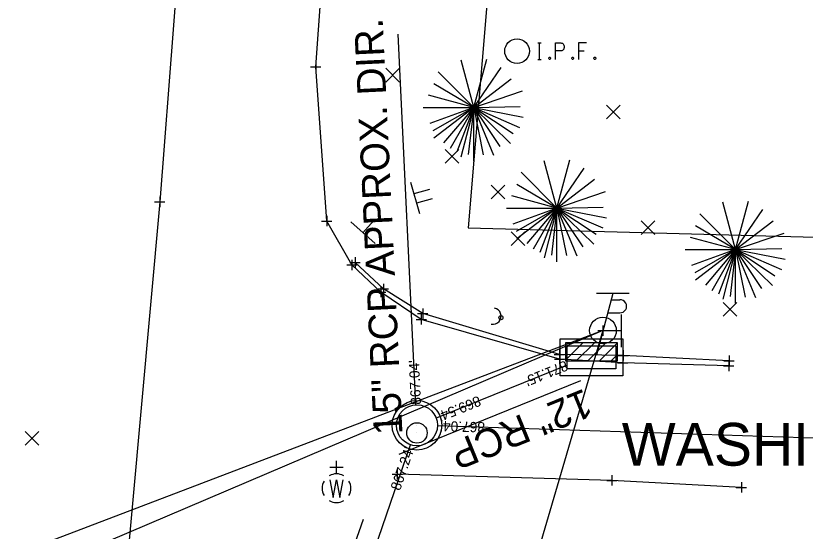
# Model space of a CAD drawing. Extents: x 1380550 to 1381945, y 468927 to 470496.
# Drawn here: x 1381608.3 to 1381685.3, y 470227.8 to 470278.1 of the extents above; entities that cross this region are included whole.
import ezdxf

# ---------------------------------------------------------------- set-up
doc = ezdxf.new("R2010")
doc.units = 0
for name, color, linetype in [('DR_X_Cells', 7, 'Continuous'), ('DR_X_Storm_Sewer', 7, 'Continuous'), ('DR_X_Text', 7, 'Continuous'), ('GK_Drainage_Nodes', 7, 'Continuous'), ('PV_X_COP', 7, 'Continuous'), ('PV_X_Curb', 7, 'Continuous'), ('PV_X_EOP', 7, 'Continuous'), ('RC_X_Text', 7, 'Continuous'), ('RW_X_Esmt_General', 7, 'Continuous'), ('SC_Scratch1', 7, 'Continuous'), ('SN_X_Public', 7, 'Continuous'), ('SV_X_Mon_Cells_Found', 7, 'Continuous'), ('SV_X_Random_Point', 7, 'Continuous'), ('SV_X_Shot_Marker', 7, 'Continuous'), ('UT_X_Electric', 7, 'Continuous'), ('UT_X_Misc_Cells', 7, 'Continuous'), ('UT_X_Telecom', 7, 'Continuous'), ('UT_X_Water_Cells', 7, 'Continuous'), ('VG_X_Cells', 7, 'Continuous')]:
    doc.layers.add(name, color=color, linetype=linetype)

msp = doc.modelspace()

# ---------------------------------------------------------------- linework, layer by layer
at = {"layer": 'DR_X_Cells'}
for p, q in [((1381662.499, 470246.25), (1381661.944, 470245.694)), ((1381663.629, 470246.25), (1381661.944, 470244.561)), ((1381664.759, 470246.25), (1381662.93, 470244.417)), ((1381665.888, 470246.25), (1381664.06, 470244.417)), ((1381666.944, 470246.176), (1381665.19, 470244.417)), ((1381666.944, 470245.043), (1381666.32, 470244.417))]:
    msp.add_line(p, q, dxfattribs=at)
for points in [[(1381667.486, 470242.999), (1381661.402, 470242.999), (1381661.402, 470246.583), (1381667.486, 470246.583)], [(1381666.944, 470244.417), (1381661.944, 470244.417), (1381661.944, 470246.25), (1381666.944, 470246.25)], [(1381666.819, 470243.667), (1381662.069, 470243.667), (1381662.069, 470245.917), (1381666.819, 470245.917)]]:
    msp.add_lwpolyline(points, close=True, dxfattribs=at)
for centre, radius in [((1381647.426, 470238.171), 2.417), ((1381647.426, 470238.171), 2), ((1381647.426, 470237.421), 1)]:
    msp.add_circle(centre, radius, dxfattribs=at)
at = {"layer": 'DR_X_Storm_Sewer'}
for p, q in [((1381647.33, 470240.169), (1381645.602, 470276.308)), ((1381662.069, 470244.042), (1381649.304, 470238.86)), ((1381940.268, 470228.716), (1381649.425, 470238.106)), ((1381633.903, 470198.558), (1381646.794, 470236.273))]:
    msp.add_line(p, q, dxfattribs=at)
at = {"layer": 'DR_X_Text'}
for p, q in [((1381645.705, 470235.349), (1381663.39, 470242.528)), ((1381642.166, 470228.993), (1381635.993, 470210.933))]:
    msp.add_line(p, q, dxfattribs=at)
at = {"layer": 'GK_Drainage_Nodes'}
for p, q in [((1381664.444, 470246.583), (1381664.444, 470246.583)), ((1381664.444, 470245.917), (1381664.444, 470245.917)), ((1381662.069, 470244.792), (1381662.069, 470244.792)), ((1381664.444, 470244.792), (1381664.444, 470244.792)), ((1381666.819, 470244.792), (1381666.819, 470244.792)), ((1381664.444, 470244.417), (1381664.444, 470244.417)), ((1381664.444, 470244.417), (1381664.444, 470244.417)), ((1381664.444, 470243.667), (1381664.444, 470243.667)), ((1381664.444, 470243), (1381664.444, 470243)), ((1381647.426, 470240.171), (1381647.426, 470240.171)), ((1381647.426, 470238.171), (1381647.426, 470238.171)), ((1381647.426, 470238.171), (1381647.426, 470238.171)), ((1381647.426, 470237.421), (1381647.426, 470237.421)), ((1381647.426, 470236.171), (1381647.426, 470236.171))]:
    msp.add_line(p, q, dxfattribs=at)
msp.add_circle((1381647.426, 470238.171), 2, dxfattribs=at)
at = {"layer": 'PV_X_COP'}
for points in [[(1381627.408, 470324.235), (1381625.025, 470294.425), (1381622.344, 470259.947), (1381618.765, 470220.138), (1381616.919, 470200.188), (1381615.103, 470178.831), (1381610.946, 470124.776), (1381606.492, 470071.232), (1381602.26, 470019.361), (1381598.177, 469969.796), (1381595.011, 469928.064), (1381590.91, 469878.811), (1381589.36, 469859.114), (1381585.986, 469815.579), (1381581.288, 469760.779)], [(1381679.062, 470232.112), (1381666.426, 470232.791), (1381645.502, 470233.392)]]:
    msp.add_lwpolyline(points, dxfattribs=at)
at = {"layer": 'PV_X_Curb'}
msp.add_lwpolyline([(1381677.862, 470244.458), (1381667.541, 470244.981), (1381661.311, 470245.064), (1381647.994, 470249.052), (1381644.157, 470251.471), (1381641.388, 470254.052)], dxfattribs=at)
at = {"layer": 'PV_X_EOP'}
msp.add_lwpolyline([(1381677.821, 470243.959), (1381667.493, 470244.246), (1381661.321, 470244.629), (1381647.841, 470248.496), (1381643.906, 470251.149), (1381641.086, 470253.807), (1381638.634, 470258.076), (1381637.552, 470273.11), (1381639.286, 470297.033), (1381641.369, 470320.574)], dxfattribs=at)
at = {"layer": 'RW_X_Esmt_General'}
msp.add_lwpolyline([(1381668.019, 470443.901), (1381652.434, 470257.404), (1381784.265, 470253.874)], dxfattribs=at)
at = {"layer": 'SN_X_Public'}
for p, q in [((1381647.706, 470258.769), (1381646.84, 470261.849)), ((1381647.143, 470260.771), (1381648.683, 470261.204)), ((1381647.273, 470260.309), (1381647.273, 470260.309)), ((1381647.403, 470259.847), (1381648.943, 470260.28)), ((1381643.347, 470255.876), (1381640.965, 470258.014)), ((1381642.156, 470256.945), (1381643.225, 470258.136)), ((1381667.345, 470248.969), (1381667.345, 470245.769)), ((1381667.345, 470247.369), (1381665.745, 470247.369))]:
    msp.add_line(p, q, dxfattribs=at)
at = {"layer": 'SV_X_Mon_Cells_Found'}
for points in [[(1381659.198, 470275.448), (1381659.551, 470275.448)], [(1381659.375, 470273.848), (1381659.375, 470275.448)], [(1381660.94, 470273.848), (1381660.94, 470275.448), (1381661.469, 470275.448), (1381661.524, 470275.435), (1381661.601, 470275.41), (1381661.635, 470275.385), (1381661.668, 470275.36), (1381661.712, 470275.297), (1381661.745, 470275.234), (1381661.767, 470275.133), (1381661.767, 470274.982), (1381661.756, 470274.931), (1381661.734, 470274.856), (1381661.69, 470274.768), (1381661.645, 470274.73), (1381661.612, 470274.705), (1381661.557, 470274.679), (1381661.469, 470274.667), (1381660.94, 470274.667)], [(1381663.949, 470275.448), (1381663.189, 470275.448), (1381663.189, 470273.848)], [(1381663.189, 470274.667), (1381663.729, 470274.667)], [(1381659.198, 470273.848), (1381659.551, 470273.848)], [(1381660.334, 470274.062), (1381660.389, 470274.062), (1381660.422, 470274.037), (1381660.455, 470273.987), (1381660.455, 470273.924), (1381660.422, 470273.873), (1381660.389, 470273.848), (1381660.334, 470273.848), (1381660.301, 470273.873), (1381660.268, 470273.924), (1381660.268, 470273.987), (1381660.301, 470274.037), (1381660.334, 470274.062)], [(1381662.583, 470274.062), (1381662.638, 470274.062), (1381662.671, 470274.037), (1381662.704, 470273.987), (1381662.704, 470273.924), (1381662.671, 470273.873), (1381662.638, 470273.848), (1381662.583, 470273.848), (1381662.549, 470273.873), (1381662.516, 470273.924), (1381662.516, 470273.987), (1381662.549, 470274.037), (1381662.583, 470274.062)], [(1381664.732, 470274.062), (1381664.787, 470274.062), (1381664.82, 470274.037), (1381664.853, 470273.987), (1381664.853, 470273.924), (1381664.82, 470273.873), (1381664.787, 470273.848), (1381664.732, 470273.848), (1381664.699, 470273.873), (1381664.666, 470273.924), (1381664.666, 470273.987), (1381664.699, 470274.037), (1381664.732, 470274.062)]]:
    msp.add_lwpolyline(points, dxfattribs=at)
msp.add_circle((1381657.184, 470274.648), 1.2, dxfattribs=at)
at = {"layer": 'SV_X_Random_Point'}
for p, q in [((1381644.396, 470271.637), (1381645.73, 470272.972)), ((1381644.396, 470272.972), (1381645.73, 470271.637)), ((1381665.897, 470268.046), (1381667.231, 470269.381)), ((1381665.897, 470269.381), (1381667.231, 470268.046)), ((1381650.161, 470263.722), (1381651.495, 470265.057)), ((1381650.161, 470265.057), (1381651.495, 470263.722)), ((1381654.657, 470260.249), (1381655.991, 470261.584)), ((1381654.657, 470261.584), (1381655.991, 470260.249)), ((1381669.274, 470256.769), (1381670.608, 470258.104)), ((1381669.274, 470258.104), (1381670.608, 470256.769)), ((1381656.603, 470255.684), (1381657.937, 470257.019)), ((1381656.603, 470257.019), (1381657.937, 470255.684)), ((1381677.295, 470248.818), (1381678.629, 470250.153)), ((1381677.295, 470250.153), (1381678.629, 470248.818)), ((1381609.232, 470236.233), (1381610.566, 470237.568)), ((1381609.232, 470237.568), (1381610.566, 470236.233))]:
    msp.add_line(p, q, dxfattribs=at)
at = {"layer": 'SV_X_Shot_Marker'}
for p, q in [((1381637.052, 470273.11), (1381638.052, 470273.11)), ((1381637.552, 470273.61), (1381637.552, 470272.61)), ((1381637.552, 470273.11), (1381637.552, 470273.11)), ((1381621.844, 470259.947), (1381622.844, 470259.947)), ((1381622.344, 470260.447), (1381622.344, 470259.447)), ((1381622.344, 470259.947), (1381622.344, 470259.947)), ((1381638.634, 470258.576), (1381638.634, 470257.576)), ((1381638.134, 470258.076), (1381639.134, 470258.076)), ((1381638.634, 470258.076), (1381638.634, 470258.076)), ((1381641.388, 470254.552), (1381641.388, 470253.552)), ((1381640.586, 470253.807), (1381641.586, 470253.807)), ((1381640.888, 470254.052), (1381641.888, 470254.052)), ((1381641.086, 470254.307), (1381641.086, 470253.307)), ((1381641.086, 470253.807), (1381641.086, 470253.807)), ((1381641.388, 470254.052), (1381641.388, 470254.052)), ((1381643.657, 470251.471), (1381644.657, 470251.471)), ((1381643.657, 470251.471), (1381644.657, 470251.471)), ((1381643.906, 470251.649), (1381643.906, 470250.649)), ((1381643.906, 470251.649), (1381643.906, 470250.649)), ((1381644.157, 470251.971), (1381644.157, 470250.971)), ((1381644.157, 470251.971), (1381644.157, 470250.971)), ((1381644.157, 470251.471), (1381644.157, 470251.471)), ((1381644.157, 470251.471), (1381644.157, 470251.471)), ((1381643.406, 470251.149), (1381644.406, 470251.149)), ((1381643.406, 470251.149), (1381644.406, 470251.149)), ((1381643.906, 470251.149), (1381643.906, 470251.149)), ((1381643.906, 470251.149), (1381643.906, 470251.149)), ((1381647.994, 470249.552), (1381647.994, 470248.552)), ((1381647.341, 470248.496), (1381648.341, 470248.496)), ((1381647.494, 470249.052), (1381648.494, 470249.052)), ((1381647.841, 470248.996), (1381647.841, 470247.996)), ((1381647.841, 470248.496), (1381647.841, 470248.496)), ((1381647.994, 470249.052), (1381647.994, 470249.052)), ((1381665.562, 470247.904), (1381665.562, 470246.904)), ((1381665.562, 470247.904), (1381665.562, 470246.904)), ((1381665.562, 470247.904), (1381665.562, 470246.904)), ((1381665.562, 470247.904), (1381665.562, 470246.904)), ((1381665.562, 470247.904), (1381665.562, 470246.904)), ((1381665.062, 470247.404), (1381666.062, 470247.404)), ((1381665.062, 470247.404), (1381666.062, 470247.404)), ((1381665.062, 470247.404), (1381666.062, 470247.404)), ((1381665.062, 470247.404), (1381666.062, 470247.404)), ((1381665.062, 470247.404), (1381666.062, 470247.404)), ((1381665.562, 470247.404), (1381665.562, 470247.404)), ((1381665.562, 470247.404), (1381665.562, 470247.404)), ((1381665.562, 470247.404), (1381665.562, 470247.404)), ((1381665.562, 470247.404), (1381665.562, 470247.404)), ((1381665.562, 470247.404), (1381665.562, 470247.404)), ((1381661.311, 470245.564), (1381661.311, 470244.564)), ((1381661.311, 470245.564), (1381661.311, 470244.564)), ((1381667.541, 470245.481), (1381667.541, 470244.481)), ((1381660.811, 470245.064), (1381661.811, 470245.064)), ((1381660.811, 470245.064), (1381661.811, 470245.064)), ((1381660.821, 470244.629), (1381661.821, 470244.629)), ((1381660.821, 470244.629), (1381661.821, 470244.629)), ((1381661.311, 470245.064), (1381661.311, 470245.064)), ((1381661.311, 470245.064), (1381661.311, 470245.064)), ((1381661.321, 470245.129), (1381661.321, 470244.129)), ((1381661.321, 470245.129), (1381661.321, 470244.129)), ((1381661.321, 470244.629), (1381661.321, 470244.629)), ((1381661.321, 470244.629), (1381661.321, 470244.629)), ((1381667.041, 470244.981), (1381668.041, 470244.981)), ((1381667.493, 470244.746), (1381667.493, 470243.746)), ((1381667.541, 470244.981), (1381667.541, 470244.981)), ((1381677.862, 470244.958), (1381677.862, 470243.958)), ((1381666.993, 470244.246), (1381667.993, 470244.246)), ((1381667.493, 470244.246), (1381667.493, 470244.246)), ((1381677.321, 470243.959), (1381678.321, 470243.959)), ((1381677.362, 470244.458), (1381678.362, 470244.458)), ((1381677.821, 470244.459), (1381677.821, 470243.459)), ((1381677.821, 470243.959), (1381677.821, 470243.959)), ((1381677.862, 470244.458), (1381677.862, 470244.458)), ((1381645.502, 470233.892), (1381645.502, 470232.892)), ((1381645.002, 470233.392), (1381646.002, 470233.392)), ((1381645.502, 470233.392), (1381645.502, 470233.392)), ((1381666.426, 470233.291), (1381666.426, 470232.291)), ((1381665.926, 470232.791), (1381666.926, 470232.791)), ((1381666.426, 470232.791), (1381666.426, 470232.791)), ((1381679.062, 470232.612), (1381679.062, 470231.612)), ((1381678.562, 470232.112), (1381679.562, 470232.112)), ((1381679.062, 470232.112), (1381679.062, 470232.112))]:
    msp.add_line(p, q, dxfattribs=at)
at = {"layer": 'UT_X_Electric'}
for points in [[(1381665.562, 470247.404), (1381595.795, 470220.833), (1381581.264, 470018.199), (1381571.968, 469887.64), (1381559.775, 469757.408), (1381543.86, 469565.781), (1381529.165, 469390.12), (1381515.279, 469203.101), (1381540.8, 469054.263)], [(1381665.562, 470247.404), (1381657.035, 470218.369)]]:
    msp.add_lwpolyline(points, dxfattribs=at)
at = {"layer": 'UT_X_Misc_Cells'}
for p, q in [((1381666.525, 470251.004), (1381664.919, 470245.004)), ((1381668.125, 470251.004), (1381664.925, 470251.004)), ((1381666.365, 470250.404), (1381667.215, 470250.404)), ((1381666.024, 470249.129), (1381667.215, 470249.129))]:
    msp.add_line(p, q, dxfattribs=at)
for centre, radius in [((1381655.614, 470248.66), 0.2), ((1381665.562, 470247.404), 1.3)]:
    msp.add_circle(centre, radius, dxfattribs=at)
for centre, radius, start, end in [((1381667.228, 470249.767), 0.638, 268.8767, 91.1233), ((1381654.829, 470248.816), 0.8, 258.74526, 78.74526)]:
    msp.add_arc(centre, radius, start, end, dxfattribs=at)
at = {"layer": 'UT_X_Telecom'}
msp.add_lwpolyline([(1381665.562, 470247.404), (1381595.346, 470217.51), (1381581.264, 470018.199), (1381571.968, 469887.64), (1381559.775, 469757.408), (1381543.86, 469565.781), (1381529.165, 469390.12), (1381515.279, 469203.101), (1381540.8, 469054.263)], dxfattribs=at)
at = {"layer": 'UT_X_Water_Cells'}
for p, q in [((1381639.582, 470233.429), (1381639.582, 470234.701)), ((1381640.217, 470234.066), (1381638.945, 470234.066)), ((1381639.582, 470232.029), (1381639.582, 470232.029))]:
    msp.add_line(p, q, dxfattribs=at)
msp.add_lwpolyline([(1381638.945, 470232.849), (1381639.264, 470231.126), (1381639.582, 470232.849), (1381639.902, 470231.126), (1381640.219, 470232.849)], dxfattribs=at)
for start, end in [(60.01836, 120.01574), (150.01836, 209.98164), (330.01836, 29.98164), (239.98426, 299.98164)]:
    msp.add_arc((1381639.582, 470232.03), 1.4, start, end, dxfattribs=at)
at = {"layer": 'VG_X_Cells'}
for p, q in [((1381652.969, 470269.158), (1381651.734, 470273.772)), ((1381652.969, 470269.158), (1381654.226, 470273.857)), ((1381652.969, 470269.158), (1381655.624, 470273.043)), ((1381652.969, 470269.158), (1381649.479, 470272.645)), ((1381652.969, 470269.158), (1381656.626, 470271.963)), ((1381652.969, 470269.158), (1381649.062, 470271.455)), ((1381652.969, 470269.158), (1381657.706, 470270.765)), ((1381652.969, 470269.158), (1381648.556, 470270.342)), ((1381648.034, 470269.158), (1381652.969, 470269.158)), ((1381652.969, 470269.158), (1381648.679, 470267.597)), ((1381652.969, 470269.158), (1381648.986, 470266.877)), ((1381652.969, 470269.158), (1381649.062, 470266.163)), ((1381652.969, 470269.158), (1381650.024, 470265.692)), ((1381652.969, 470269.158), (1381650.651, 470265.143)), ((1381652.969, 470269.158), (1381651.304, 470264.818)), ((1381652.969, 470269.158), (1381651.706, 470264.302)), ((1381652.969, 470269.158), (1381652.427, 470264.567)), ((1381652.969, 470269.158), (1381657.479, 470269.25)), ((1381652.969, 470263.918), (1381652.969, 470269.158)), ((1381652.969, 470269.158), (1381653.891, 470264.522)), ((1381652.969, 470269.158), (1381654.902, 470264.49)), ((1381652.969, 470269.158), (1381655.506, 470265.365)), ((1381652.969, 470269.158), (1381656.557, 470265.637)), ((1381652.969, 470269.158), (1381656.791, 470266.603)), ((1381652.969, 470269.158), (1381657.434, 470267.217)), ((1381652.969, 470269.158), (1381657.797, 470268.2)), ((1381661.078, 470259.349), (1381659.843, 470263.963)), ((1381661.078, 470259.349), (1381662.335, 470264.048)), ((1381661.078, 470259.349), (1381663.733, 470263.234)), ((1381661.078, 470259.349), (1381657.588, 470262.836)), ((1381661.078, 470259.349), (1381657.171, 470261.646)), ((1381661.078, 470259.349), (1381664.735, 470262.154)), ((1381661.078, 470259.349), (1381665.815, 470260.956)), ((1381661.078, 470259.349), (1381656.665, 470260.533)), ((1381678.497, 470255.307), (1381677.262, 470259.92)), ((1381678.497, 470255.307), (1381679.754, 470260.005)), ((1381656.143, 470259.349), (1381661.078, 470259.349)), ((1381661.078, 470259.349), (1381656.788, 470257.788)), ((1381661.078, 470259.349), (1381657.095, 470257.068)), ((1381661.078, 470259.349), (1381657.171, 470256.354)), ((1381661.078, 470259.349), (1381658.133, 470255.883)), ((1381661.078, 470259.349), (1381658.76, 470255.334)), ((1381661.078, 470259.349), (1381659.413, 470255.009)), ((1381661.078, 470259.349), (1381659.815, 470254.493)), ((1381661.078, 470259.349), (1381660.536, 470254.758)), ((1381661.078, 470259.349), (1381665.588, 470259.441)), ((1381661.078, 470254.109), (1381661.078, 470259.349)), ((1381661.078, 470259.349), (1381662, 470254.713)), ((1381661.078, 470259.349), (1381663.011, 470254.681)), ((1381661.078, 470259.349), (1381663.615, 470255.556)), ((1381661.078, 470259.349), (1381664.666, 470255.828)), ((1381661.078, 470259.349), (1381664.9, 470256.794)), ((1381661.078, 470259.349), (1381665.543, 470257.408)), ((1381661.078, 470259.349), (1381665.906, 470258.391)), ((1381678.497, 470255.307), (1381681.152, 470259.192)), ((1381678.497, 470255.307), (1381675.007, 470258.793)), ((1381678.497, 470255.307), (1381674.59, 470257.603)), ((1381678.497, 470255.307), (1381682.154, 470258.112)), ((1381678.497, 470255.307), (1381683.234, 470256.913)), ((1381678.497, 470255.307), (1381674.084, 470256.49)), ((1381673.562, 470255.307), (1381678.497, 470255.307)), ((1381678.497, 470255.307), (1381674.207, 470253.745)), ((1381678.497, 470255.307), (1381674.514, 470253.025)), ((1381678.497, 470255.307), (1381674.59, 470252.312)), ((1381678.497, 470255.307), (1381675.552, 470251.84)), ((1381678.497, 470255.307), (1381676.179, 470251.292)), ((1381678.497, 470255.307), (1381676.832, 470250.967)), ((1381678.497, 470255.307), (1381677.234, 470250.45)), ((1381678.497, 470255.307), (1381677.955, 470250.715)), ((1381678.497, 470255.307), (1381683.007, 470255.398)), ((1381678.497, 470250.067), (1381678.497, 470255.307)), ((1381678.497, 470255.307), (1381679.419, 470250.67)), ((1381678.497, 470255.307), (1381680.43, 470250.638)), ((1381678.497, 470255.307), (1381681.034, 470251.513)), ((1381678.497, 470255.307), (1381682.085, 470251.785)), ((1381678.497, 470255.307), (1381682.319, 470252.752)), ((1381678.497, 470255.307), (1381682.962, 470253.365)), ((1381678.497, 470255.307), (1381683.325, 470254.348))]:
    msp.add_line(p, q, dxfattribs=at)

# ---------------------------------------------------------------- texts
at = {"layer": 'DR_X_Text'}
for s, rotation, p in [('15" RCP APPROX. DIR.', 92.73872, (1381646.018, 470237.293)), ('12" RCP', 202.09342, (1381663.755, 470241.787))]:
    msp.add_text(s, height=2.8, rotation=rotation, dxfattribs=at).set_placement(p)
at = {"layer": 'RC_X_Text'}
msp.add_text('WASHINGTON AVE.', height=4.16667, dxfattribs=at).set_placement((1381667.396, 470234.228))
at = {"layer": 'SC_Scratch1'}
for s, rotation, p in [("867.04'", 92.73872, (1381647.83, 470240.193)), ("871.15'", 202.09342, (1381661.881, 470244.505)), ("869.54'", 202.09342, (1381653.408, 470241.066)), ("867.04'", 178.15078, (1381654.071, 470238.457)), ("867.24'", 71.12967, (1381645.769, 470231.728))]:
    msp.add_text(s, height=1, rotation=rotation, dxfattribs=at).set_placement(p)

doc.saveas('drawing.dxf')
